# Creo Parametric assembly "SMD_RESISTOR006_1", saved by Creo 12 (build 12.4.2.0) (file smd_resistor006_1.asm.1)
Units: Custom; MM, KILOGRAM, SECS

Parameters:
  PTC_WM_ITERATION = "0"
  PTC_WM_VERSION = "-.0"
  PTC_WM_LIFECYCLE_STATE = "In Work"
  PTC_WM_LIFECYCLE = "MO_CADDocument"
  PTC_WM_CREATED_BY = "Maximilian Roepper (Z0017RMS: MO)"
  PTC_WM_CREATED_ON = "18-Sep-26 11:36:42 AM"
  PTC_WM_MODIFIED_BY = "Maximilian Roepper (Z0017RMS: MO)"
  PTC_WM_MODIFIED_ON = "18-Sep-26 11:36:46 AM"
  PDMLINKNUMBER = "PDM000071454827"
  PTC_WM_NUMBER = "PDM000071454827"

Other parameters: WEIGHT, WEIGHT_FACTOR, WEIGHT_ADD, MC_ERRORS, SUPPLIER

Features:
  1. coordinate system
  2. imported feature
  3. component "BODY007_1"
  4. component "CONTACT024_1"
  5. component "CONTACT025_1"
  6. component "LABEL005_1"
  7. component "PART021_1"

Other named items: DRW_VIEW_ORG, ROUGH-GROB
